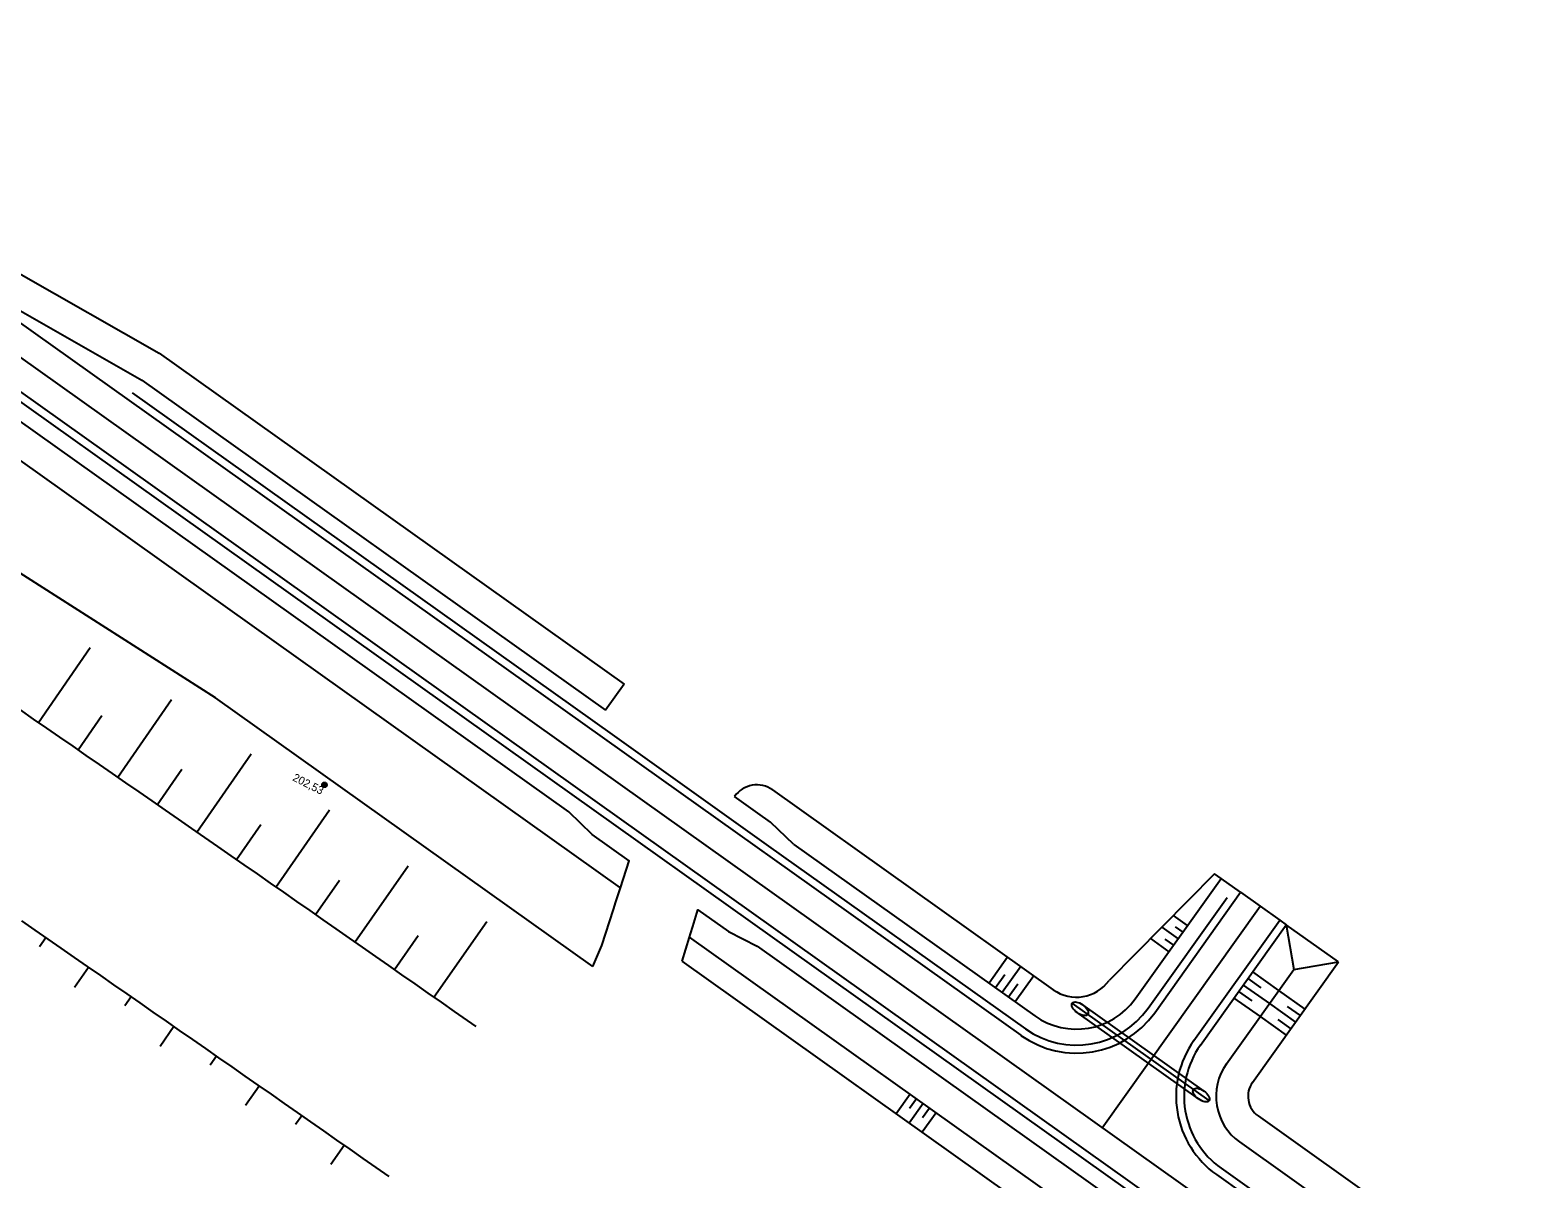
# Model space of a CAD drawing. Extents: x -552278 to -547230, y -1151007 to -1148251.
# Drawn here: x -550177.8 to -550083.9, y -1149135.8 to -1149064 of the extents above; entities that cross this region are included whole.
import ezdxf

# ---------------------------------------------------------------- set-up
doc = ezdxf.new("R2010")
doc.units = 0
doc.layers.add('SO221815_VYSKOPIS', color=7, linetype='Continuous')
doc.layers.add('u_trat navrh', color=7, linetype='Continuous')

# ---------------------------------------------------------------- blocks, each defined once
blk = doc.blocks.new('SO221824_VYSKOPIS')
at = {"layer": 'SO221815_VYSKOPIS'}
for p, q in [((1.23, -0.85), (-1.23, 0.85)), ((0.86, 1.23), (-0.86, -1.23)), ((0.86, 1.23), (0, 0)), ((0, 0), (1.23, -0.85))]:
    blk.add_line(p, q, dxfattribs=at)
blk.add_lwpolyline([(-0.86, -1.23), (0, 0), (-1.23, 0.85)], dxfattribs=at)
blk.add_circle((0, 0), 1.5, dxfattribs=at)
for start, end in [(145.36204, 235.15382), (325.36204, 55.15382)]:
    blk.add_arc((0, 0), 1.5, start, end, dxfattribs=at)

msp = doc.modelspace()

# ---------------------------------------------------------------- linework, layer by layer
at = {"layer": 'u_trat navrh'}
for p, q in [((-550204.162, -1149064.038), (-550115.928, -1149126.867)), ((-550205.177, -1149065.464), (-550087.554, -1149149.22)), ((-550206.192, -1149066.889), (-550088.569, -1149150.645)), ((-550144.163, -1149112.9), (-550207.062, -1149068.111)), ((-550140.946, -1149117.646), (-550208.222, -1149069.74)), ((-550166.235, -1149105.784), (-550216.282, -1149073.844)), ((-550178.522, -1149079.231), (-550169.759, -1149084.239)), ((-550179.601, -1149080.918), (-550170.838, -1149085.926)), ((-550169.759, -1149084.239), (-550140.719, -1149104.918)), ((-550170.838, -1149085.926), (-550141.88, -1149106.547)), ((-550177.305, -1149107.322), (-550174.07, -1149102.634)), ((-550140.719, -1149104.918), (-550141.88, -1149106.547)), ((-550172.355, -1149110.742), (-550168.989, -1149105.877)), ((-550142.677, -1149122.563), (-550166.235, -1149105.784)), ((-550174.829, -1149109.031), (-550173.344, -1149106.882)), ((-550167.41, -1149114.168), (-550164.017, -1149109.279)), ((-550169.882, -1149112.454), (-550168.347, -1149110.239)), ((-550131.435, -1149111.528), (-550113.898, -1149124.016)), ((-550162.47, -1149117.601), (-550159.111, -1149112.773)), ((-550164.939, -1149115.884), (-550163.42, -1149113.698)), ((-550130.1, -1149114.934), (-550115.058, -1149125.645)), ((-550157.534, -1149121.04), (-550154.205, -1149116.268)), ((-550160.001, -1149119.32), (-550158.497, -1149117.16)), ((-550103.823, -1149116.765), (-550110.412, -1149123.43)), ((-550108.783, -1149124.59), (-550103.416, -1149117.055)), ((-550103.416, -1149117.055), (-550103.823, -1149116.765)), ((-550102.194, -1149117.925), (-550103.416, -1149117.055)), ((-550107.561, -1149125.46), (-550102.194, -1149117.925)), ((-550102.194, -1149117.925), (-550099.751, -1149119.666)), ((-550110.835, -1149132.643), (-550100.973, -1149118.796)), ((-550106.41, -1149119.381), (-550105.523, -1149120.013)), ((-550152.601, -1149124.484), (-550149.299, -1149119.762)), ((-550107.122, -1149120.102), (-550106.103, -1149120.827)), ((-550106.289, -1149120.081), (-550105.813, -1149120.42)), ((-550105.117, -1149127.2), (-550099.751, -1149119.666)), ((-550104.709, -1149127.49), (-550099.344, -1149119.956)), ((-550099.751, -1149119.666), (-550099.344, -1149119.956)), ((-550096.085, -1149122.276), (-550099.344, -1149119.956)), ((-550099.344, -1149119.956), (-550098.875, -1149122.745)), ((-550176.845, -1149120.768), (-550177.238, -1149121.336)), ((-550155.067, -1149122.761), (-550153.575, -1149120.625)), ((-550104.357, -1149143.7), (-550136.622, -1149120.725)), ((-550103.389, -1149141.934), (-550132.385, -1149121.287)), ((-550107.834, -1149120.822), (-550106.683, -1149121.642)), ((-550106.935, -1149120.848), (-550106.393, -1149121.235)), ((-550105.166, -1149144.966), (-550137.087, -1149122.235)), ((-550116.749, -1149121.986), (-550117.909, -1149123.615)), ((-550101.451, -1149129.81), (-550096.085, -1149122.276)), ((-550098.875, -1149122.745), (-550096.085, -1149122.276)), ((-550174.177, -1149122.618), (-550175.049, -1149123.875)), ((-550116.922, -1149123.091), (-550117.502, -1149123.905)), ((-550115.934, -1149122.566), (-550117.095, -1149124.195)), ((-550115.12, -1149123.146), (-550116.28, -1149124.775)), ((-550103.08, -1149128.65), (-550098.875, -1149122.745)), ((-550101.446, -1149122.908), (-550099.817, -1149124.068)), ((-550116.107, -1149123.671), (-550116.688, -1149124.485)), ((-550102.316, -1149124.13), (-550101.502, -1149124.71)), ((-550102.026, -1149123.723), (-550100.397, -1149124.883)), ((-550101.736, -1149123.315), (-550100.922, -1149123.896)), ((-550099.817, -1149124.068), (-550098.188, -1149125.229)), ((-550171.51, -1149124.469), (-550171.901, -1149125.032)), ((-550104.167, -1149130.945), (-550112.719, -1149124.856)), ((-550104.48, -1149130.354), (-550112.057, -1149124.96)), ((-550102.607, -1149124.537), (-550100.977, -1149125.698)), ((-550100.397, -1149124.883), (-550098.768, -1149126.043)), ((-550099.293, -1149125.056), (-550098.478, -1149125.636)), ((-550104.829, -1149130.842), (-550112.405, -1149125.449)), ((-550100.977, -1149125.698), (-550099.348, -1149126.858)), ((-550099.873, -1149125.87), (-550099.058, -1149126.451)), ((-550168.845, -1149126.322), (-550169.71, -1149127.566)), ((-550166.18, -1149128.177), (-550166.567, -1149128.732)), ((-550163.517, -1149130.034), (-550164.37, -1149131.256)), ((-550122.848, -1149130.547), (-550123.718, -1149131.769)), ((-550122.034, -1149131.127), (-550122.904, -1149132.349)), ((-550122.441, -1149130.837), (-550122.876, -1149131.448)), ((-550121.626, -1149131.417), (-550122.061, -1149132.028)), ((-550160.855, -1149131.892), (-550161.235, -1149132.436)), ((-550121.219, -1149131.707), (-550122.089, -1149132.929)), ((-550101.099, -1149131.903), (-550083.929, -1149144.129)), ((-550102.257, -1149133.533), (-550085.089, -1149145.758)), ((-550158.194, -1149133.752), (-550159.03, -1149134.947)), ((-550103.416, -1149135.163), (-550086.249, -1149147.387)), ((-550103.706, -1149135.571), (-550086.539, -1149147.795))]:
    msp.add_line(p, q, dxfattribs=at)
for points in [[(-550102.809, -1149141.119), (-550132.807, -1149119.759), (-550142.581, -1149112.799), (-550206.482, -1149067.297)], [(-550171.455, -1149086.714), (-550141.458, -1149108.074), (-550131.683, -1149115.035), (-550115.638, -1149126.46)], [(-550178.453, -1149106.53), (-550177.629, -1149107.098), (-550176.806, -1149107.666), (-550175.982, -1149108.235), (-550175.158, -1149108.803), (-550174.335, -1149109.372), (-550173.512, -1149109.941), (-550172.689, -1149110.511), (-550171.866, -1149111.08), (-550171.043, -1149111.65), (-550170.22, -1149112.22), (-550169.398, -1149112.79), (-550168.575, -1149113.36), (-550167.753, -1149113.93), (-550166.931, -1149114.501), (-550166.109, -1149115.071), (-550165.287, -1149115.642), (-550164.465, -1149116.213), (-550163.643, -1149116.784), (-550162.822, -1149117.356), (-550162, -1149117.927), (-550161.179, -1149118.499), (-550160.358, -1149119.071), (-550159.537, -1149119.643), (-550158.716, -1149120.215), (-550157.895, -1149120.788), (-550157.074, -1149121.36), (-550156.254, -1149121.933), (-550155.433, -1149122.505), (-550154.613, -1149123.078), (-550153.793, -1149123.652), (-550152.973, -1149124.225), (-550152.153, -1149124.798), (-550151.333, -1149125.372), (-550150.513, -1149125.945), (-550149.975, -1149126.322)], [(-550130.1, -1149114.934), (-550131.562, -1149113.537), (-550132.35, -1149112.975), (-550133.811, -1149111.935)], [(-550142.677, -1149122.563), (-550142.101, -1149121.251), (-550141.382, -1149118.997), (-550141.229, -1149118.521), (-550140.946, -1149117.646), (-550140.402, -1149115.958), (-550142.713, -1149114.311), (-550144.168, -1149112.907), (-550144.163, -1149112.9)], [(-550107.968, -1149125.17), (-550103.043, -1149118.256)], [(-550137.087, -1149122.235), (-550136.622, -1149120.725), (-550136.563, -1149120.533), (-550136.418, -1149120.055), (-550136.105, -1149119.018), (-550134.194, -1149120.379), (-550132.391, -1149121.295), (-550132.385, -1149121.287)], [(-550178.362, -1149119.718), (-550177.54, -1149120.287), (-550176.719, -1149120.856), (-550175.898, -1149121.425), (-550175.076, -1149121.994), (-550174.255, -1149122.564), (-550173.434, -1149123.133), (-550172.613, -1149123.703), (-550171.792, -1149124.273), (-550170.972, -1149124.843), (-550170.151, -1149125.414), (-550169.33, -1149125.984), (-550168.51, -1149126.555), (-550167.69, -1149127.126), (-550166.87, -1149127.697), (-550166.05, -1149128.268), (-550165.23, -1149128.839), (-550164.41, -1149129.411), (-550163.59, -1149129.983), (-550162.771, -1149130.554), (-550161.951, -1149131.126), (-550161.132, -1149131.699), (-550160.312, -1149132.271), (-550159.493, -1149132.843), (-550158.674, -1149133.416), (-550157.855, -1149133.989), (-550157.036, -1149134.562), (-550156.218, -1149135.135), (-550155.412, -1149135.699)]]:
    msp.add_lwpolyline(points, dxfattribs=at)
for centre, radius, start, end in [((-550132.421, -1149112.913), 1.7, 54.54627, 144.85565), ((-550112.448, -1149121.98), 2.5, 234.54627, 324.5401), ((-550112.448, -1149121.98), 4.5, 234.54627, 324.5401), ((-550112.448, -1149121.98), 6, 234.54627, 324.5401), ((-550112.448, -1149121.98), 5.5, 234.54627, 324.5401), ((-550100.229, -1149130.68), 6, 144.5401, 234.59088), ((-550100.229, -1149130.68), 5.5, 144.5401, 234.59088), ((-550100.229, -1149130.68), 3.5, 144.5401, 234.59088), ((-550100.229, -1149130.68), 1.5, 144.5401, 234.59088)]:
    msp.add_arc(centre, radius, start, end, dxfattribs=at)
for centre in [(-550112.231, -1149125.204), (-550104.654, -1149130.598)]:
    msp.add_ellipse(centre, major_axis=(0.489, -0.348), ratio=0.5, dxfattribs=at)

# ---------------------------------------------------------------- block references
at = {"layer": 'u_trat navrh', "xscale": 0.1, "yscale": 0.09999999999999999, "rotation": -31.851985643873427}
msp.add_blockref('SO221824_VYSKOPIS', (-550159.438, -1149111.214), dxfattribs=at)

# ---------------------------------------------------------------- texts
at = {"layer": 'u_trat navrh'}
msp.add_text('202,53', height=0.5, rotation=333.25678, dxfattribs=at).set_placement((-550161.473, -1149110.919))

doc.saveas('drawing.dxf')
